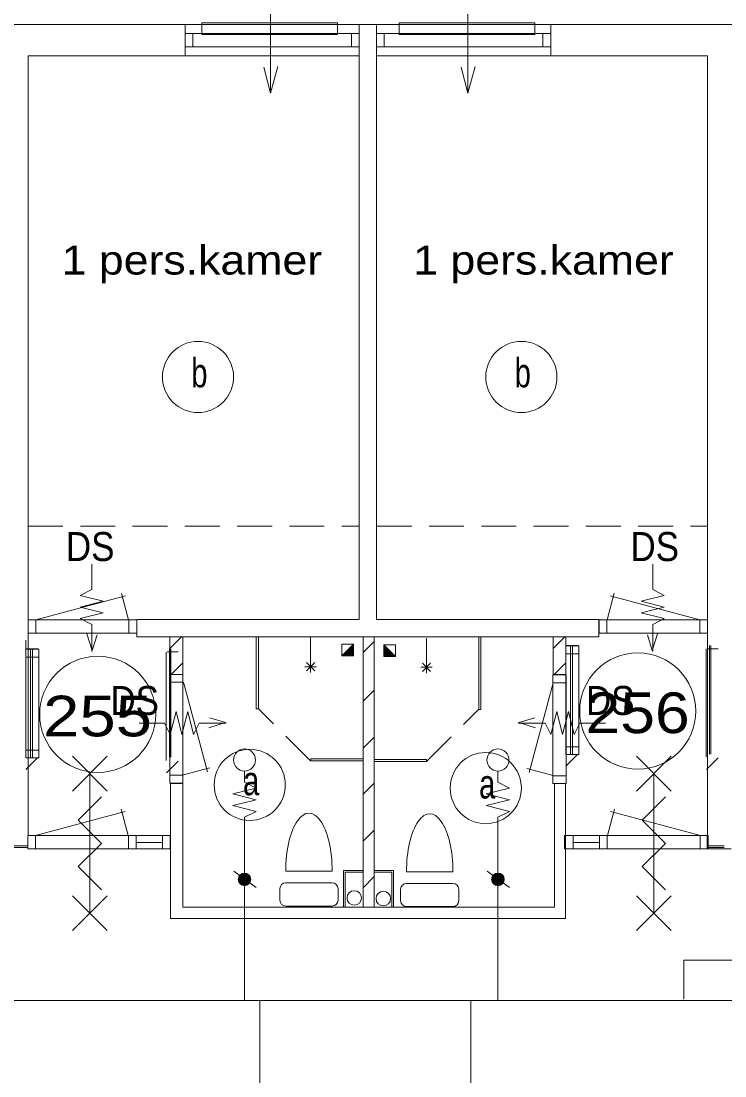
# Model space of a CAD drawing. Extents: x 295824 to 414724, y 24924 to 109024.
# Drawn here: x 320029 to 326089, y 95369 to 104447 of the extents above; entities that cross this region are included whole.
import ezdxf
from ezdxf.enums import TextEntityAlignment as Align

# ---------------------------------------------------------------- set-up
doc = ezdxf.new("R2010")
doc.units = 0
doc.header["$LTSCALE"] = 100
doc.linetypes.add('MEDIUM_DASHED', pattern=[4.5, 3, -1.5])
for name, color, linetype, lineweight in [('1', 7, 'Continuous', 13), ('16', 7, 'Continuous', 13), ('24', 7, 'Continuous', 13), ('61', 7, 'Continuous', 13)]:
    doc.layers.add(name, color=color, linetype=linetype, lineweight=lineweight)

msp = doc.modelspace()

# ---------------------------------------------------------------- hatches: boundary and pattern name
at = {"layer": '24'}
for points in [[(322006.8, 97060.5, 1), (321898.2, 97060.5, 1)], [(324188.8, 97060.5, 1), (324080.2, 97060.5, 1)]]:
    msp.add_hatch(color=256, dxfattribs=at).paths.add_polyline_path(points)
at = {"layer": '61'}
for points in [[(322789.5, 98985.1), (322889.5, 99085.1), (322889.5, 98985.1)], [(323251.9, 98979.7), (323151.9, 99079.7), (323151.9, 98979.7)]]:
    msp.add_hatch(color=256, dxfattribs=at).paths.add_polyline_path(points)

# ---------------------------------------------------------------- linework, layer by layer
at = {"layer": '1'}
for p, q in [((321952.5, 97029.2), (321952.5, 96018.7)), ((324134.5, 97022.5), (324134.5, 96018.7)), ((322085.8, 95135.8), (322085.8, 96018.7)), ((323901.3, 95130.8), (323901.3, 96018.7))]:
    msp.add_line(p, q, dxfattribs=at)
at = {"layer": '16'}
for p, q in [((320536.7, 99404.1), (320736.7, 99454.1)), ((325567, 99404.1), (325367, 99454.1)), ((321413.1, 98305.9), (321363.1, 98505.9)), ((324690.6, 98305.9), (324740.6, 98505.9))]:
    msp.add_line(p, q, dxfattribs=at)
at = {"layer": '24'}
for p, q in [((322177.4, 103826.9), (322117.8, 104049.3)), ((323876.3, 103826.9), (323816.7, 104049.3)), ((320640.1, 99028.7), (320595, 99172.8)), ((320682.5, 99164.5), (320640.1, 99028.7)), ((325421.2, 99164.5), (325463.6, 99028.7)), ((325463.6, 99028.7), (325508.6, 99172.8)), ((321788.5, 98409.3), (321644.3, 98364.2)), ((321652.7, 98451.7), (321788.5, 98409.3)), ((324451, 98451.7), (324315.2, 98409.3)), ((324315.2, 98409.3), (324459.3, 98364.2)), ((321952.5, 97545.9), (321952.5, 97006.4)), ((324134.5, 97545.9), (324134.5, 97037.5)), ((321860.9, 97131.3), (322052.5, 96989.6)), ((324042.9, 97131.3), (324234.4, 96989.6)), ((304113.6, 96018.7), (328710.3, 96018.7))]:
    msp.add_line(p, q, dxfattribs=at)
for points in [[(322177.4, 104801.9), (322177.4, 103826.9), (322239.1, 104057.1)], [(323876.3, 104801.9), (323876.3, 103826.9), (323938, 104057.1)], [(320736.7, 99454.1), (320536.7, 99504.1), (320636.7, 99554.1), (320636.7, 99772.8)], [(325367, 99454.1), (325567, 99504.1), (325467, 99554.1), (325467, 99772.8)], [(320636.7, 99022.8), (320636.7, 99254.1), (320536.7, 99304.1), (320736.7, 99354.1), (320536.7, 99404.1)], [(325467, 99022.8), (325467, 99254.1), (325567, 99304.1), (325367, 99354.1), (325567, 99404.1)], [(321363.1, 98505.9), (321313.1, 98305.9), (321263.1, 98405.9), (321044.4, 98405.9)], [(321794.4, 98405.9), (321563.1, 98405.9), (321513.1, 98305.9), (321463.1, 98505.9), (321413.1, 98305.9)], [(324309.3, 98405.9), (324540.6, 98405.9), (324590.6, 98305.9), (324640.6, 98505.9), (324690.6, 98305.9)], [(324740.6, 98505.9), (324790.6, 98305.9), (324840.6, 98405.9), (325059.3, 98405.9)], [(321952.5, 97995.9), (321952.5, 97895.9), (322052.5, 97845.9), (321852.5, 97795.9), (322052.5, 97745.9), (321852.5, 97695.9), (322052.5, 97645.9), (321952.5, 97595.9), (321952.5, 97545.9)], [(324134.5, 97995.9), (324134.5, 97895.9), (324234.5, 97845.9), (324034.5, 97795.9), (324234.5, 97745.9), (324034.5, 97695.9), (324234.5, 97645.9), (324134.5, 97595.9), (324134.5, 97545.9)], [(325734.2, 96030.8), (325734.2, 96364.1), (328199.4, 96364.1)]]:
    msp.add_lwpolyline(points, dxfattribs=at)
for points in [[(321586.1, 104331), (322752, 104331), (322752, 104431), (321586.1, 104431)], [(323285, 104331), (324451, 104331), (324451, 104431), (323285, 104431)]]:
    msp.add_lwpolyline(points, close=True, dxfattribs=at)
for centre, radius in [((321952.5, 98087.5), 95), ((324134.5, 98087.5), 95), ((321952.5, 97060.5), 54.3), ((324134.5, 97060.5), 54.3)]:
    msp.add_circle(centre, radius, dxfattribs=at)
at = {"layer": '61'}
for p, q in [((321440.7, 104147.6), (321440.7, 104417.6)), ((322940.1, 104417.5), (322940.1, 99297.6)), ((323090.1, 104409.9), (323090.1, 99297.6)), ((324588.7, 104147.6), (324588.7, 104417.8)), ((321507.5, 104225.9), (321507.5, 104339.8)), ((322872.5, 104225.3), (322872.5, 104339.3)), ((323156, 104226.2), (323156, 104340.2)), ((324520.3, 104225.9), (324520.3, 104339.6)), ((320090.1, 104147.6), (322940.1, 104147.6)), ((320090.1, 97436.7), (320090.1, 104147.6)), ((325940.1, 104147.6), (323090.1, 104147.6)), ((325940.1, 97322.6), (325940.1, 104147.6)), ((320156.3, 99293.7), (320929, 99500.7)), ((320954.7, 99294.3), (320893.9, 99521.1)), ((325074.1, 99295.4), (325134.9, 99522.2)), ((325872.5, 99294.8), (325099.8, 99501.8)), ((320157.1, 99179), (320157.1, 99293)), ((320957.1, 99179), (320957.1, 99293)), ((321024.1, 99179), (321024.1, 99293)), ((325004.7, 99180.1), (325004.7, 99294.1)), ((325071.7, 99180.1), (325071.7, 99294.1)), ((325871.7, 99180.1), (325871.7, 99294.1)), ((321309.2, 99046.8), (321408.9, 99146.5)), ((321310.7, 98823), (321310.7, 99147)), ((321310.7, 99147), (321420.7, 99147)), ((321420.7, 98823), (321420.7, 99147)), ((322072, 99147.4), (322072, 98526.9)), ((322521.8, 98940.9), (322521.8, 99140.9)), ((322973.8, 99147.6), (322973.8, 96822.6)), ((323070.1, 99147.6), (323070.1, 96822.6)), ((323519.5, 98935.5), (323519.5, 99135.5)), ((323969.4, 99142), (323969.4, 98521.5)), ((324609.7, 98823), (324609.7, 99147)), ((324609.7, 99147), (324719.7, 99147)), ((324611.4, 99046.8), (324711.1, 99146.5)), ((324719.7, 98823), (324719.7, 99147)), ((320070.2, 98795.1), (320070.2, 99119.2)), ((320176.8, 99044.2), (320071.6, 99044.2)), ((320110.3, 98108.2), (320110.3, 99040.6)), ((320126.1, 98108.2), (320126.1, 99040.6)), ((320182.8, 98108.2), (320182.8, 99040.6)), ((321307.4, 98110.9), (321307.4, 99044.9)), ((321318.4, 98110.9), (321318.4, 99044.9)), ((322974.4, 99011.5), (323070.1, 99107.3)), ((324826.3, 99072.1), (324721, 99072.1)), ((324759.8, 98136.1), (324759.8, 99068.5)), ((324775.6, 98136.1), (324775.6, 99068.5)), ((324832.2, 98136.1), (324832.2, 99068.5)), ((325928, 98110.9), (325928, 99044.9)), ((326030.3, 99045.7), (325935.5, 99045.7)), ((325956.9, 98138.8), (325956.9, 99072.8)), ((325967.9, 98138.8), (325967.9, 99072.8)), ((320182.8, 98973.6), (320068.8, 98973.6)), ((321278.6, 98083), (321278.6, 99017)), ((321380.8, 99017.8), (321286.1, 99017.8)), ((324832.2, 99001.5), (324718.2, 99001.5)), ((321321.5, 98824.2), (321421.2, 98923.9)), ((322571.8, 98890.9), (322471.8, 98890.9)), ((322557.2, 98926.2), (322486.4, 98855.5)), ((322557.2, 98855.5), (322486.4, 98926.2)), ((322521.8, 98940.9), (322521.8, 98840.9)), ((323469.5, 98885.5), (323569.5, 98885.5)), ((323484.2, 98920.9), (323554.9, 98850.2)), ((323484.2, 98850.2), (323554.9, 98920.9)), ((323519.5, 98935.5), (323519.5, 98835.5)), ((324620, 98824.2), (324719.7, 98923.9)), ((321308.9, 98822.1), (321308.9, 97889.7)), ((321310.7, 98823), (321420.7, 98823)), ((324609, 98819.4), (324723, 98819.4)), ((324609.7, 98823), (324719.7, 98823)), ((324722.4, 98819.4), (324722.4, 97885.4)), ((321308.9, 98756.7), (321422.9, 98756.7)), ((321426.1, 98757.4), (321633.2, 97984.7)), ((322974.4, 98593.4), (323070.1, 98689.2)), ((324610.3, 98753.2), (324403.3, 97980.5)), ((324722.4, 98752.4), (324608.4, 98752.4)), ((322974.4, 98188.8), (323070.1, 98284.6)), ((320182.8, 98173.6), (320068.8, 98173.6)), ((324832.2, 98201.5), (324718.2, 98201.5)), ((324819.6, 98134), (324719.9, 98034.3)), ((324830.4, 98135.2), (324720.5, 98135.2)), ((320170.2, 98106.1), (320070.5, 98006.4)), ((320181, 98107.4), (320071, 98107.4)), ((320771, 98119.9), (320471, 97819.9)), ((320471, 98119.9), (320771, 97819.9)), ((321381, 98078.3), (321281.3, 97978.6)), ((322972, 98097.4), (322522.9, 98097.4)), ((322522.9, 98079.4), (322522.9, 98097.4)), ((322972.3, 98079.4), (322522.9, 98079.4)), ((323069, 98074), (323518.5, 98074)), ((323069.3, 98092), (323518.5, 98092)), ((323518.5, 98074), (323518.5, 98092)), ((325626.8, 98119.9), (325326.8, 97819.9)), ((325326.8, 98119.9), (325626.8, 97819.9)), ((326030.4, 98106.1), (325930.7, 98006.4)), ((320621, 96769.9), (320621, 97969.9)), ((321308.9, 97956.7), (321422.9, 97956.7)), ((321426.7, 97959), (321653.6, 98019.8)), ((324609.7, 97954.8), (324382.8, 98015.6)), ((324722.4, 97952.4), (324608.4, 97952.4)), ((325476.8, 96769.9), (325476.8, 97969.9)), ((321314.9, 97886.1), (321314.9, 97320.2)), ((321314.9, 97886.1), (321420.1, 97886.1)), ((322974.4, 97792.8), (323070.1, 97888.6)), ((324620.1, 97884.6), (324620.1, 96822.6)), ((324620.1, 97884.6), (324714.9, 97884.6)), ((324714.9, 97884.6), (324714.9, 97422.6)), ((320152.9, 97437.3), (320925.7, 97644.4)), ((320951.3, 97437.9), (320890.6, 97664.8)), ((325078.7, 97437.9), (325139.4, 97664.8)), ((325877.1, 97437.3), (325104.3, 97644.4)), ((320153.7, 97322.7), (320153.7, 97436.7)), ((320953.7, 97322.7), (320953.7, 97436.7)), ((321020.7, 97322.7), (321020.7, 97436.7)), ((321246.7, 97322.7), (321246.7, 97436.7)), ((322974.4, 97389.4), (323070.1, 97485.2)), ((324783.3, 97322.7), (324783.3, 97436.7)), ((325009.3, 97322.7), (325009.3, 97436.7)), ((325076.3, 97322.7), (325076.3, 97436.7)), ((325876.3, 97322.7), (325876.3, 97436.7)), ((319943.6, 97348.9), (320084.8, 97348.9)), ((319943.6, 97333.9), (320084.8, 97333.9)), ((321246.7, 97376.8), (321020.7, 97376.8)), ((324783.3, 97376.8), (325009.3, 97376.8)), ((325931.5, 97322.6), (326141.5, 97322.6)), ((325942.4, 97348.9), (326083.6, 97348.9)), ((325942.4, 97333.9), (326083.6, 97333.9)), ((322707.5, 97130.5), (322307.5, 97130.5)), ((322820, 97123.1), (322970, 97123.1)), ((322820, 96823.1), (322820, 97123.1)), ((322974.4, 96988.5), (323070.1, 97084.3)), ((323070.1, 97122.6), (323220.1, 97122.6)), ((323220.1, 97122.6), (323220.1, 96822.6)), ((323746.9, 97125.6), (323346.9, 97125.6)), ((322257.5, 96880.5), (322257.5, 96980.5)), ((322307.5, 97030.5), (322707.5, 97030.5)), ((322757.5, 96980.5), (322757.5, 96880.5)), ((323296.9, 96875.6), (323296.9, 96975.6)), ((323346.9, 97025.6), (323746.9, 97025.6)), ((323796.9, 96975.6), (323796.9, 96875.6)), ((320771, 96919.9), (320471, 96619.9)), ((320471, 96919.9), (320771, 96619.9)), ((325626.8, 96919.9), (325326.8, 96619.9)), ((325326.8, 96919.9), (325626.8, 96619.9)), ((322707.5, 96830.5), (322307.5, 96830.5)), ((323746.9, 96825.6), (323346.9, 96825.6))]:
    msp.add_line(p, q, dxfattribs=at)
at = {"layer": '61', "linetype": 'MEDIUM_DASHED'}
for p, q in [((320089.5, 100101), (322938.6, 100101)), ((323091.9, 100101), (325938.9, 100101)), ((322520.8, 98079.8), (322073.9, 98526.7)), ((323520.5, 98074.4), (323967.4, 98521.3))]:
    msp.add_line(p, q, dxfattribs=at)
at = {"layer": '61'}
for points in [[(301796.6, 92184.5), (301820.1, 104417.6), (332210.1, 104417.6)], [(320090.1, 99179), (320090.1, 99293), (321024.1, 99293)], [(321024.1, 99179), (320090.1, 99179), (320090.1, 99293)], [(322939.9, 99297.6), (321024.9, 99297.6), (321024.9, 99147.6), (325004.2, 99147.6)], [(323089.9, 99297.6), (325004.2, 99297.6), (325004.2, 99147.6)], [(325938.7, 99180.1), (325938.7, 99294.1), (325004.7, 99294.1)], [(325004.7, 99180.1), (325938.7, 99180.1), (325938.7, 99294.1)], [(322054, 99147.4), (322054, 98526.9), (322072, 98526.9)], [(323987.4, 99142), (323987.4, 98521.5), (323969.4, 98521.5)], [(322889.5, 99085.1), (322889.5, 98985.1), (322789.5, 98985.1)], [(323151.9, 99079.7), (323151.9, 98979.7), (323251.9, 98979.7)], [(321420.1, 97886.1), (321420.1, 96822.6), (324620.1, 96822.6)], [(320721, 96969.9), (320521, 97169.9), (320721, 97369.9), (320521, 97569.9), (320721, 97769.9)], [(325576.8, 96969.9), (325376.8, 97169.9), (325576.8, 97369.9), (325376.8, 97569.9), (325576.8, 97769.9)], [(321314.9, 97322.6), (321314.9, 96722.6), (324714.9, 96722.6), (324714.9, 97322.6)], [(322805, 96823.1), (322805, 97138.1), (322970, 97138.1)], [(323070.1, 97137.6), (323235.1, 97137.6), (323235.1, 96822.6)]]:
    msp.add_lwpolyline(points, dxfattribs=at)
for points in [[(321440.6, 104225.8), (321440.6, 104339.8), (322939.3, 104339.8), (322939.3, 104225.8)], [(323089.6, 104225.9), (323089.6, 104339.9), (324589, 104339.9), (324589, 104225.9)], [(320182.8, 99041.6), (320068.8, 99041.6), (320068.8, 98107.6), (320182.8, 98107.6)], [(322889.5, 99085.1), (322789.5, 99085.1), (322789.5, 98985.1)], [(322789.5, 98985.1), (322889.5, 99085.1), (322889.5, 98985.1)], [(323151.9, 99079.7), (323251.9, 99079.7), (323251.9, 98979.7)], [(323251.9, 98979.7), (323151.9, 99079.7), (323151.9, 98979.7)], [(324832.2, 99069.4), (324718.2, 99069.4), (324718.2, 98135.4), (324832.2, 98135.4)], [(321308.9, 97888.7), (321422.9, 97888.7), (321422.9, 98822.7), (321308.9, 98822.7)], [(324722.4, 98819.4), (324722.4, 97885.4), (324608.4, 97885.4), (324608.4, 98819.4)], [(320086.7, 97322.7), (320086.7, 97436.7), (321313.1, 97436.7), (321313.1, 97322.7)], [(320086.7, 97322.7), (320086.7, 97436.7), (321313.1, 97436.7), (321313.1, 97322.7)], [(324708, 97322.7), (324708, 97436.7), (325935, 97436.7), (325935, 97322.7)], [(324716.3, 97322.7), (324716.3, 97436.7), (325943.3, 97436.7), (325943.3, 97322.7)]]:
    msp.add_lwpolyline(points, close=True, dxfattribs=at)
for centre, radius in [((321552.2, 101384.2), 306.3), ((324336.3, 101384.2), 306.3), ((320688.9, 98481.1), 500), ((325338.3, 98509), 500), ((321997.6, 97873.7), 306.3), ((324030, 97845.8), 306.3), ((322897.6, 96900.6), 62.5), ((323147.6, 96895), 62.5)]:
    msp.add_circle(centre, radius, dxfattribs=at)
for centre, start, end in [((322307.5, 96980.5), 90, 180), ((322707.5, 96980.5), 0, 90), ((323346.9, 96975.6), 90, 180), ((323746.9, 96975.6), 0, 90), ((322307.5, 96880.5), 180, 270), ((322707.5, 96880.5), 270, 0), ((323346.9, 96875.6), 180, 270), ((323746.9, 96875.6), 270, 0)]:
    msp.add_arc(centre, 50, start, end, dxfattribs=at)
for centre in [(322507.5, 97130.5), (323546.9, 97125.6)]:
    msp.add_ellipse(centre, major_axis=(0, 500), ratio=0.4, start_param=4.712389, end_param=7.853982, dxfattribs=at)

# ---------------------------------------------------------------- texts
at = {"layer": '24', "width": 0.9}
for p in [(320414.9, 99799.9), (325275.5, 99799.9), (320797.9, 98474.9), (324892.4, 98474.9)]:
    msp.add_text('DS', height=250, dxfattribs=at).set_placement(p)
at = {"layer": '61'}
for s, width, p in [('1 pers.kamer', 1.15, (320377.7, 102265.6)), ('1 pers.kamer', 1.15, (323404.8, 102265.6)), ('b', 0.75, (321494.2, 101295)), ('b', 0.75, (324278.3, 101295)), ('a', 0.75, (321939.6, 97784.5)), ('a', 0.75, (323972, 97756.6))]:
    msp.add_text(s, height=250, dxfattribs=dict(at, width=width)).set_placement(p)
for s, width, p in [('255', 1.2, (320687.3, 98291.2)), ('256', 1.15, (325336.8, 98319.1))]:
    msp.add_text(s, height=350, dxfattribs=dict(at, width=width)).set_placement(p, align=Align.CENTER)

doc.saveas('drawing.dxf')
